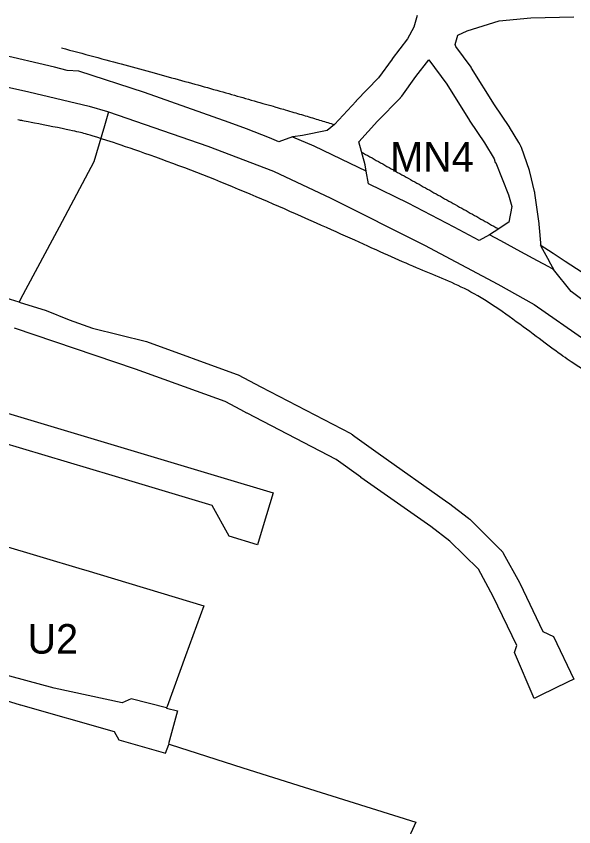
# Model space of a CAD drawing. Extents: x 7413438 to 7416393, y 5541665 to 5544118.
# Drawn here: x 7414738.9 to 7414851.9, y 5542699.5 to 5542863.7 of the extents above; entities that cross this region are included whole.
import ezdxf

# ---------------------------------------------------------------- set-up
doc = ezdxf.new("R2010")
doc.units = 0
for name, color, linetype in [('linie_rozgraniczajace', 7, 'Continuous'), ('linie_zabudowy_nieprzekraczalne', 7, 'Continuous'), ('oznaczenia_przeznaczen', 7, 'Continuous')]:
    doc.layers.add(name, color=color, linetype=linetype)

msp = doc.modelspace()

# ---------------------------------------------------------------- linework, layer by layer
at = {"layer": 'linie_rozgraniczajace'}
for p, q in [((7414820.21, 5542863.86), (7414819.49, 5542861.51)), ((7414836.82, 5542862.8), (7414843.21, 5542863.4)), ((7414843.21, 5542863.4), (7414851.94, 5542863.63)), ((7414830.33, 5542860.79), (7414836.82, 5542862.8)), ((7414819.49, 5542861.51), (7414818.24, 5542859.19)), ((7414828.4, 5542859.9), (7414830.33, 5542860.79)), ((7414818.24, 5542859.19), (7414815.14, 5542855.12)), ((7414827.86, 5542858.03), (7414828.4, 5542859.9)), ((7414828.01, 5542857.61), (7414827.86, 5542858.03)), ((7414831.09, 5542853.41), (7414828.01, 5542857.61)), ((7414746.66, 5542853.39), (7414734.97, 5542856.15)), ((7414815.14, 5542855.12), (7414815.1, 5542855.06)), ((7414815.1, 5542855.06), (7414812.32, 5542851.23)), ((7414819.94, 5542851.51), (7414822.54, 5542854.93)), ((7414822.54, 5542854.93), (7414826.18, 5542849.95)), ((7414749.25, 5542852.77), (7414746.66, 5542853.39)), ((7414751.57, 5542852.61), (7414749.25, 5542852.77)), ((7414764.88, 5542848.3), (7414751.57, 5542852.61)), ((7414831.09, 5542853.4), (7414831.09, 5542853.41)), ((7414831.21, 5542853.24), (7414831.09, 5542853.4)), ((7414831.21, 5542853.22), (7414831.21, 5542853.24)), ((7414835.85, 5542845.8), (7414831.21, 5542853.22)), ((7414812.32, 5542851.23), (7414807.84, 5542846.6)), ((7414817.06, 5542847.54), (7414819.94, 5542851.51)), ((7414733.74, 5542850.13), (7414741.44, 5542848.45)), ((7414826.18, 5542849.95), (7414830.79, 5542842.58)), ((7414741.44, 5542848.45), (7414753.72, 5542845.51)), ((7414782.04, 5542842.22), (7414764.88, 5542848.3)), ((7414812.17, 5542842.45), (7414816.78, 5542847.21)), ((7414816.78, 5542847.21), (7414816.83, 5542847.27)), ((7414816.83, 5542847.27), (7414816.96, 5542847.41)), ((7414816.96, 5542847.41), (7414817.06, 5542847.54)), ((7414753.72, 5542845.51), (7414757.43, 5542844.47)), ((7414807.79, 5542846.55), (7414803.41, 5542841.8)), ((7414807.84, 5542846.6), (7414807.79, 5542846.55)), ((7414838.83, 5542841.37), (7414835.85, 5542845.8)), ((7414757.63, 5542844.4), (7414757.07, 5542842.48)), ((7414757.43, 5542844.47), (7414757.63, 5542844.4)), ((7414757.63, 5542844.4), (7414777.74, 5542837.44)), ((7414757.07, 5542842.48), (7414756.79, 5542841.53)), ((7414785.57, 5542840.91), (7414782.04, 5542842.22)), ((7414808.34, 5542838.29), (7414812.17, 5542842.45)), ((7414830.79, 5542842.58), (7414830.8, 5542842.56)), ((7414830.8, 5542842.56), (7414830.84, 5542842.49)), ((7414830.84, 5542842.49), (7414833.81, 5542838.08)), ((7414756.79, 5542841.53), (7414754.64, 5542834.25)), ((7414790.26, 5542839.12), (7414785.57, 5542840.91)), ((7414801.93, 5542840.57), (7414796.96, 5542839.56)), ((7414803.41, 5542841.8), (7414801.93, 5542840.57)), ((7414838.88, 5542841.3), (7414838.83, 5542841.37)), ((7414838.91, 5542841.24), (7414838.88, 5542841.3)), ((7414840.76, 5542838.17), (7414838.91, 5542841.24)), ((7414792.15, 5542838.29), (7414790.26, 5542839.12)), ((7414794.9, 5542839.28), (7414792.15, 5542838.29)), ((7414794.98, 5542839.29), (7414794.9, 5542839.28)), ((7414796.96, 5542839.56), (7414794.98, 5542839.29)), ((7414795, 5542839.24), (7414794.98, 5542839.29)), ((7414799.27, 5542837.43), (7414795, 5542839.24)), ((7414777.74, 5542837.44), (7414791.06, 5542832.38)), ((7414806.57, 5542833.88), (7414799.27, 5542837.43)), ((7414809.62, 5542833.62), (7414808.34, 5542838.29)), ((7414833.81, 5542838.08), (7414835.76, 5542834.85)), ((7414841.06, 5542837.68), (7414840.76, 5542838.17)), ((7414841.12, 5542837.56), (7414841.06, 5542837.68)), ((7414841.21, 5542837.39), (7414841.12, 5542837.56)), ((7414841.29, 5542837.21), (7414841.21, 5542837.39)), ((7414841.32, 5542837.11), (7414841.29, 5542837.21)), ((7414842.93, 5542832.46), (7414841.32, 5542837.11)), ((7414754.64, 5542834.25), (7414747.6, 5542821.02)), ((7414809.87, 5542832.35), (7414806.57, 5542833.88)), ((7414835.76, 5542834.85), (7414836, 5542834.13)), ((7414836, 5542834.13), (7414836.14, 5542834.04)), ((7414836.14, 5542834.04), (7414838.69, 5542827.57)), ((7414791.06, 5542832.38), (7414802.65, 5542826.89)), ((7414809.87, 5542832.35), (7414809.62, 5542833.62)), ((7414810.29, 5542829.81), (7414809.87, 5542832.35)), ((7414842.95, 5542832.38), (7414842.93, 5542832.46)), ((7414843, 5542832.21), (7414842.95, 5542832.38)), ((7414843.99, 5542828.24), (7414843, 5542832.21)), ((7414818.32, 5542825.84), (7414810.29, 5542829.81)), ((7414838.69, 5542827.57), (7414839.36, 5542825.22)), ((7414843.99, 5542828.22), (7414843.99, 5542828.24)), ((7414844.03, 5542828.03), (7414843.99, 5542828.22)), ((7414844.05, 5542827.92), (7414844.03, 5542828.03)), ((7414844.89, 5542821.77), (7414844.05, 5542827.92)), ((7414802.65, 5542826.89), (7414821.63, 5542817.37)), ((7414827.66, 5542820.99), (7414818.32, 5542825.84)), ((7414839.36, 5542825.22), (7414838.76, 5542822.03)), ((7414747.6, 5542821.02), (7414746.18, 5542818.35)), ((7414832.77, 5542818.28), (7414827.66, 5542820.99)), ((7414838.76, 5542822.03), (7414835.8, 5542820.08)), ((7414844.9, 5542821.68), (7414844.89, 5542821.77)), ((7414844.9, 5542821.64), (7414844.9, 5542821.68)), ((7414845.32, 5542817.09), (7414844.9, 5542821.64)), ((7414834.85, 5542819.45), (7414832.77, 5542818.28)), ((7414835.8, 5542820.08), (7414834.85, 5542819.45)), ((7414837.16, 5542818.21), (7414834.85, 5542819.45)), ((7414746.18, 5542818.35), (7414739.8, 5542806.42)), ((7414821.63, 5542817.37), (7414836.5, 5542809.45)), ((7414841.19, 5542816.02), (7414837.16, 5542818.21)), ((7414844.54, 5542814.19), (7414841.19, 5542816.02)), ((7414847, 5542814.03), (7414845.32, 5542817.09)), ((7414846.84, 5542812.96), (7414844.54, 5542814.19)), ((7414847.01, 5542814.02), (7414847, 5542814.03)), ((7414847.02, 5542814.02), (7414847.01, 5542814.02)), ((7414847.02, 5542814), (7414847.02, 5542814.02)), ((7414847.81, 5542812.44), (7414846.84, 5542812.96)), ((7414847.9, 5542812.39), (7414847.02, 5542814)), ((7414851.41, 5542807.97), (7414847.81, 5542812.44)), ((7414847.81, 5542812.44), (7414847.9, 5542812.39)), ((7414739.48, 5542805.82), (7414725.7, 5542810.06)), ((7414836.5, 5542809.45), (7414843.88, 5542805.35)), ((7414858.91, 5542802.2), (7414851.41, 5542807.97)), ((7414739.8, 5542806.42), (7414739.48, 5542805.82)), ((7414739.48, 5542805.82), (7414745, 5542804.12)), ((7414843.88, 5542805.35), (7414854.36, 5542798.05)), ((7414745, 5542804.12), (7414749.65, 5542802.21)), ((7414749.65, 5542802.21), (7414754.35, 5542800.55)), ((7414763.07, 5542792.25), (7414738.55, 5542800.51)), ((7414754.35, 5542800.55), (7414765.31, 5542797.83)), ((7414765.31, 5542797.83), (7414783.49, 5542791.24)), ((7414781.25, 5542785.67), (7414763.07, 5542792.25)), ((7414783.49, 5542791.24), (7414783.51, 5542791.23)), ((7414783.51, 5542791.23), (7414783.69, 5542791.16)), ((7414783.69, 5542791.16), (7414783.87, 5542791.08)), ((7414783.87, 5542791.08), (7414783.89, 5542791.06)), ((7414783.89, 5542791.06), (7414788.47, 5542788.61)), ((7414788.47, 5542788.61), (7414806.71, 5542779.17)), ((7414729.21, 5542785.67), (7414780.36, 5542770.35)), ((7414784.44, 5542783.96), (7414781.25, 5542785.67)), ((7414785.66, 5542783.31), (7414784.44, 5542783.96)), ((7414785.68, 5542783.3), (7414785.66, 5542783.31)), ((7414785.69, 5542783.29), (7414785.68, 5542783.3)), ((7414803.75, 5542773.94), (7414785.69, 5542783.29)), ((7414806.71, 5542779.17), (7414806.72, 5542779.16)), ((7414806.72, 5542779.16), (7414806.89, 5542779.06)), ((7414806.89, 5542779.06), (7414807.06, 5542778.96)), ((7414807.06, 5542778.96), (7414807.09, 5542778.93)), ((7414807.09, 5542778.93), (7414812.26, 5542775.18)), ((7414758.35, 5542770.68), (7414735.75, 5542777.44)), ((7414812.26, 5542775.18), (7414826.42, 5542765.18)), ((7414808.75, 5542770.31), (7414803.75, 5542773.94)), ((7414778.64, 5542764.6), (7414758.35, 5542770.68)), ((7414780.36, 5542770.35), (7414790.98, 5542767.17)), ((7414808.78, 5542770.29), (7414808.75, 5542770.31)), ((7414822.92, 5542760.31), (7414808.78, 5542770.29)), ((7414790.98, 5542767.17), (7414788.97, 5542760.46)), ((7414826.42, 5542765.18), (7414826.51, 5542765.11)), ((7414826.51, 5542765.11), (7414830.6, 5542762)), ((7414782.08, 5542758.35), (7414778.64, 5542764.6)), ((7414830.6, 5542762), (7414830.67, 5542761.94)), ((7414830.67, 5542761.94), (7414830.82, 5542761.81)), ((7414830.82, 5542761.81), (7414830.89, 5542761.75)), ((7414830.89, 5542761.75), (7414837.1, 5542755.64)), ((7414788.97, 5542760.46), (7414787.83, 5542756.63)), ((7414826.82, 5542757.34), (7414822.92, 5542760.31)), ((7414730.03, 5542758.36), (7414752.3, 5542751.67)), ((7414787.83, 5542756.63), (7414782.08, 5542758.35)), ((7414832.58, 5542751.67), (7414826.82, 5542757.34)), ((7414837.1, 5542755.64), (7414837.17, 5542755.57)), ((7414837.17, 5542755.57), (7414837.3, 5542755.43)), ((7414837.3, 5542755.43), (7414837.42, 5542755.27)), ((7414837.42, 5542755.27), (7414837.53, 5542755.11)), ((7414837.53, 5542755.11), (7414837.62, 5542754.96)), ((7414837.62, 5542754.96), (7414840.91, 5542749)), ((7414752.3, 5542751.67), (7414753, 5542751.46)), ((7414835.61, 5542746.17), (7414832.58, 5542751.67)), ((7414753, 5542751.46), (7414776.91, 5542744.26)), ((7414840.91, 5542749), (7414840.92, 5542748.98)), ((7414840.92, 5542748.98), (7414840.98, 5542748.85)), ((7414840.98, 5542748.85), (7414845.68, 5542739.08)), ((7414840.39, 5542736.25), (7414835.61, 5542746.17)), ((7414776.91, 5542744.26), (7414773.23, 5542734.14)), ((7414845.68, 5542739.08), (7414847.81, 5542738.07)), ((7414847.81, 5542738.07), (7414851.91, 5542729.39)), ((7414839.9, 5542734.8), (7414840.39, 5542736.25)), ((7414746.62, 5542727.59), (7414721.79, 5542734.27)), ((7414773.23, 5542734.14), (7414769.47, 5542723.84)), ((7414843.86, 5542725.48), (7414839.9, 5542734.8)), ((7414850.64, 5542728.78), (7414845.24, 5542726.15)), ((7414851.91, 5542729.39), (7414850.64, 5542728.78)), ((7414726.52, 5542728.29), (7414739.72, 5542724.21)), ((7414760.41, 5542724.6), (7414746.62, 5542727.59)), ((7414762.21, 5542725.39), (7414760.41, 5542724.6)), ((7414769.37, 5542723.59), (7414762.21, 5542725.39)), ((7414845.24, 5542726.15), (7414843.86, 5542725.48)), ((7414739.72, 5542724.21), (7414739.76, 5542724.2)), ((7414739.76, 5542724.2), (7414739.79, 5542724.19)), ((7414739.79, 5542724.19), (7414758.76, 5542718.83)), ((7414769.47, 5542723.84), (7414769.38, 5542723.58)), ((7414769.38, 5542723.58), (7414769.35, 5542723.51)), ((7414769.35, 5542723.51), (7414771.58, 5542722.96)), ((7414769.38, 5542723.58), (7414769.37, 5542723.59)), ((7414771.58, 5542722.96), (7414769.8, 5542716.27)), ((7414758.76, 5542718.83), (7414759.73, 5542717.14)), ((7414759.73, 5542717.14), (7414769.15, 5542714.4)), ((7414769.15, 5542714.4), (7414769.84, 5542716.18)), ((7414769.8, 5542716.27), (7414769.92, 5542716.23)), ((7414769.84, 5542716.18), (7414769.92, 5542716.23)), ((7414769.92, 5542716.23), (7414770.09, 5542716.18)), ((7414770.09, 5542716.18), (7414784.87, 5542711.46)), ((7414784.87, 5542711.46), (7414797.25, 5542707.51)), ((7414797.25, 5542707.51), (7414819.91, 5542700.4)), ((7414819.91, 5542700.4), (7414817.78, 5542695.8))]:
    msp.add_line(p, q, dxfattribs=at)
at = {"layer": 'linie_zabudowy_nieprzekraczalne'}
for points, degree in [([(7414748.07, 5542857.34), (7414786.82, 5542846.96), (7414803.37, 5542841.78)], 2), ([(7415046.04, 5542685.6), (7415044.89, 5542688.05), (7415038.46, 5542697.69), (7415034.17, 5542702.2), (7415025.08, 5542708.44), (7415009, 5542715.33), (7414995.57, 5542721.52), (7414970.94, 5542731.05), (7414970.88, 5542731.08), (7414970.52, 5542731.25), (7414970.35, 5542731.34), (7414938.93, 5542744.38), (7414938.9, 5542744.39), (7414938.71, 5542744.46), (7414901.8, 5542759.46), (7414901.63, 5542759.53), (7414901.27, 5542759.7), (7414900.93, 5542759.89), (7414900.6, 5542760.11), (7414900.45, 5542760.22), (7414898.5, 5542761.69), (7414898.34, 5542761.82), (7414898.1, 5542762.02), (7414893.84, 5542765.85), (7414883.77, 5542771.83), (7414883.71, 5542771.87), (7414883.61, 5542771.93), (7414880.89, 5542773.67), (7414878.59, 5542776.46), (7414860.73, 5542786.52), (7414855.46, 5542791.34), (7414852.65, 5542792.67), (7414844.32, 5542798.84), (7414832.02, 5542808.01), (7414822.28, 5542811.7), (7414810.95, 5542816.79), (7414794.96, 5542824.01), (7414775.51, 5542832.34), (7414755.97, 5542839.09), (7414752.31, 5542840.07), (7414750.38, 5542840.58), (7414740.26, 5542842.54), (7414740.13, 5542842.57), (7414739.26, 5542842.76)], 3), ([(7414808.86, 5542836.23), (7414836.57, 5542820.71)], 1), ([(7414845.09, 5542817.43), (7414859.69, 5542808.04), (7414872.72, 5542798.98), (7414883.76, 5542791.57), (7414894.42, 5542785.04)], 3)]:
    msp.add_open_spline(points, degree=degree, dxfattribs=at)

# ---------------------------------------------------------------- texts
at = {"layer": 'oznaczenia_przeznaczen'}
for s, p in [('MN4', (7414814.7, 5542832.27)), ('U2', (7414741.19, 5542734.57))]:
    msp.add_text(s, height=6, dxfattribs=at).set_placement(p)

doc.saveas('drawing.dxf')
